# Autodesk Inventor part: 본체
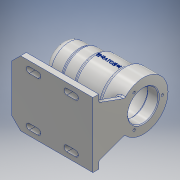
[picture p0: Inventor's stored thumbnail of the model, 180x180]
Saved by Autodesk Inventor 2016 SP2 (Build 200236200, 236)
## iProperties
Created: 2017-09
Part Number: 본체
Material: 알루미늄 6061
Document SubType Name: Modeling
Designer: Administrator
Density: 2.7 g/cm^3
Appearance: 알루미늄 - 평지
Mass: 693.606 g
Surface Area: 708.751 cm^2
Volume: 256.891 cm^3
Author: Administrator
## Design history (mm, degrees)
sketch "스케치1"
  geometry: L1 (-56, 45)-(56, 45); L2 (56, 45)-(56, -45); L3 (56, -45)-(-56, -45); L4 (-56, -45)-(-56, 45); L5 (-56, 45)-(56, -45); L6 (56, 45)-(-56, -45); 1 further point
  constraints: 12 end point, 2 midpoint, 2 parallel, 1 horizontal, 1 perpendicular
  dimensions: "d0" = 112 distance of L2.end L3.end; "d1" = 90 distance of L1.end L2.end
extrude "돌출1" new body sketch "스케치1" distance "d2" = 8; taper "d3" = 0 deg
sketch "스케치2"
  geometry: L1 (-56, -45)-(56, -45) reference; L2 (56, -45)-(56, 45) reference; L3 (56, 45)-(-56, 45) reference; L4 (-56, 45)-(-56, -45) reference; L5 (56, 45)-(-56, 45) reference; L6 (-56, -45)-(56, -45) reference; L7 (-32, -30)-(-20, -30); L8 (-20, -38)-(-32, -38); L9 (20, -30)-(32, -30); L10 (32, -38)-(20, -38); A1 r 4 centre (20, -34) between (20, -30) and (20, -38); A2 r 4 centre (32, -34) between (32, -38) and (32, -30); A3 r 4 centre (-20, -34) between (-20, -38) and (-20, -30); A4 r 4 centre (-32, -34) between (-32, -30) and (-32, -38); 5 further points
  constraints: 8 end point, 8 point on circle, 4 centre point, 2 coincident, 2 horizontal, 2 midpoint, 2 parallel, 1 collinear, 1 horizontal alignment, 1 point on line, 1 tangent
  dimensions: "d4" = 8 diameter of A1; "d5" = 8 diameter of A2; "d6" = 8 diameter of A3; "d7" = 8 diameter of A4; "d13" = 24 distance from line of A2.centre L2; "d14" = 12 distance of point (20, -34) A2.centre; "d15" = 40 distance of A3.centre point (20, -34); "d16" = 12 distance of point (-32, -34) A3.centre; "d17" = 34 vertical distance of A4.centre point (0, 0); "d19" = 8 distance between parallel lines of L8 L7
extrude "돌출2" cut sketch "스케치2" stored distance "d20" = 8; taper "d21" = 0 deg
chamfer "모따기1" distance "d22" = 12; stored, may be unused: second distance "d23" = 2, angle "d24" = 45 deg
sketch "스케치3"
  geometry: L1 (-56.618, 70)-(56, 70); L2 (56, 0)-(56, 8) reference; L3 (56, 70)-(56, 104); L4 (56, 104)-(28, 104); L5 (28, 104)-(28, 100); L6 (28, 100)-(-11, 100); L7 (-11, 100)-(-11, 97); L8 (-11, 97)-(-31, 97); L9 (-31, 97)-(-31, 95); L10 (-31, 95)-(-56, 95); L11 (-56, 95)-(-56, 70); 2 further points
  constraints: 20 end point, 8 perpendicular, 1 horizontal, 1 midpoint, 1 point on line, 1 vertical, 1 vertical alignment
  dimensions: "d26" = 70 vertical distance of point (0, 0) L1.start; "d27" = 112 distance between parallel lines of L11 L3; "d28" = 84 distance between parallel lines of L11 L5; "d29" = 45 distance between parallel lines of L11 L7; "d30" = 25 distance between parallel lines of L11 L9; "d31" = 50 diameter of L10 L1; "d32" = 54 diameter of L8 L1; "d33" = 60 diameter of L6 L1; "d34" = 68 diameter of L4 L1
revolve "회전1" sketch "스케치3" stored, may be unused: angle "d35" = 90 deg
sketch "스케치4"
  geometry: L1 (-56, 45)-(-56, 95) reference; L2 (56, 36)-(56, 104) reference; L3 (-56, 70)-(56, 70); L4 (56, 91)-(41, 91); L5 (41, 91)-(41, 94); L6 (41, 94)-(-13, 94); L7 (-13, 94)-(-13, 91); L8 (-13, 91)-(-25, 91); L9 (-25, 91)-(-25, 87.5); L10 (-25, 87.5)-(-43, 87.5); L11 (-43, 87.5)-(-43, 86); L12 (-43, 86)-(-47, 86); L13 (-47, 86)-(-47, 80.5); L14 (-47, 80.5)-(-50, 80.5); L15 (-50, 80.5)-(-50, 70); 1 further point
  constraints: 26 end point, 11 perpendicular, 4 point on line, 2 midpoint
  dimensions: "d36" = 15 distance of L4.start L4.end; "d37" = 54 distance of L5.end L6.end; "d38" = 12 distance of L7.end L8.end; "d39" = 18 distance of L9.end L10.end; "d40" = 4 distance of L11.end L12.end; "d41" = 3 distance of L13.end L14.end; "d42" = 42 diameter of L4 L3; "d43" = 48 diameter of L6 L3; "d44" = 35 diameter of L10 L3; "d45" = 32 diameter of L12 L3; "d46" = 21 diameter of L14 L3
revolve "회전2" sketch "스케치4" stored, may be unused: angle "d47" = 90 deg
sketch "스케치5"
  geometry: L1 (0, 0)-(0, 39.878); L2 (0, 0)-(-35.783, -20.659); L3 (0, 0)-(39.926, -23.051); C1 r 34 at (0, 0) reference; A1 r 26 centre (0, 0) between (0, 26) and (-22.517, -13); 2 further points
  constraints: 6 end point, 3 point on circle, 2 point on line, 1 centre point, 1 coincident, 1 vertical, 1 vertical alignment
  dimensions: "d48" = 52 diameter of A1; "d49" = 120 deg angle of L2 L1; "d50" = 120 deg angle of L3 L1
hole "구멍1" sketch "스케치5" at (0, 26), (-22.517, -13), (22.517, -13) diameter "d51" = 3.242; stored, may be unused: countersink angle "d55" = 90 deg, drill point angle "d57" = 118 deg; dims "d52" = 8, "d53" = 4, "d54" = 2, "d56" = 11
node "작업 평면1"
sketch "스케치7"
  geometry: L1 (8, 45)-(8, -45) reference; L2 (43.992, 21.9)-(8, 35); L3 (8, -33)-(8, 33) reference; L4 (43.992, -21.9)-(8, -35); L5 (0, 45)-(8, 45) reference; L6 (0, -45)-(8, -45) reference; L7 (0, 0)-(70, 0); L8 (8, 35)-(8, -35); L9 (0, 33)-(0, -33) reference; A1 r 34 centre (70, 0) between (43.992, 21.9) and (43.992, -21.9) reference
  constraints: 8 end point, 2 point on circle, 2 point on line, 1 equal length, 1 horizontal, 1 parallel
  dimensions: "d63" = 10 distance from line of L5 L2.end; "d64" = 10 distance from line of L6 L4.end; "d67" = 110 deg angle of L4 L1
extrude "돌출3" join sketch "스케치7" distance "d68" = 8; taper "d69" = 0 deg
sketch "스케치8"
  geometry: L1 (-44, 8)-(-44, 0) reference; L2 (56, 8)-(-44, 8) reference; L3 (56, 0)-(56, 8) reference; L4 (-44, 0)-(56, 0) reference; L5 (-56, 45)-(-31, 45) reference; L6 (-31, 43)-(-11, 43) reference; L7 (-11, 40)-(28, 40) reference; L8 (28, 36)-(48, 36) reference; L9 (28, 36)-(28, 104) reference; L10 (-11, 43)-(-11, 97) reference; L11 (-11, 40)-(-11, 100) reference; L12 (-31, 43)-(-31, 97) reference; L13 (56, 8)-(-44, 8) reference; L14 (-56, 0)-(-56, 8) reference; L15 (-34, 8)-(-23.014, 49); L16 (-32, 8)-(-20, 8) reference; L17 (48, 8)-(56, 8) reference; L18 (48, 8)-(-34, 8); L19 (-13, 94)-(-13, 46) reference; L20 (41, 94)-(41, 46) reference; L21 (-13, 49)-(-25, 49) reference; L22 (41, 45)-(-31, 45); 2 further points
  constraints: 6 end point, 5 point on line, 1 horizontal
  dimensions: "d75" = 105 deg angle of L2 L15; "d77" = 22 distance from line of L14 L15.start; "d86" = 41 vertical distance of L15.start L15.end
  node "투영된 루프2"
  node "투영된 루프3"
fillet "모깎기1" dims "d81" = 0.3
fillet "모깎기2" dims "d82" = 9
fillet "모깎기5" dims "d85" = 3
feature "리브1" dims "d87" = 1, "d88" = 8, "d89" = 0, "d90" = 0, "d91" = 1, "d92" = 1
fillet "모깎기6" dims "d93" = 3
fillet "모깎기7" dims "d94" = 3
fillet "모깎기11" dims "d98" = 3
fillet "모깎기12" dims "d99" = 3
fillet "모깎기13" dims "d100" = 3
node "작업 평면2"
sketch "스케치9"
  geometry: L1 (56, 45.289)-(56, 104) reference; L2 (-56, 54)-(-56, 86) reference; 3 further points
  constraints: 1 horizontal alignment, 1 midpoint, 1 other
  dimensions: "d102" = 48 distance from line of point (8, 70) L1
feature "엠보싱1" sketch "스케치9" dims "d0" = 112, "d1" = 90, "d4" = 8, "d5" = 8, "d6" = 8, "d7" = 8, "d13" = 24, "d14" = 12, "d15" = 40, "d16" = 12, "d17" = 34, "d19" = 8, "d103" = 0.5, "d104" = 0
chamfer "모따기2" distance "d105" = 1; stored, may be unused: second distance "d106" = 2, angle "d107" = 45 deg
fillet "모깎기14" dims "d108" = 3
fillet "모깎기15" dims "d109" = 3
node "솔리드1"
mirror "대칭1"
node "투영된 루프1"
other parameters: "d62" = 56
